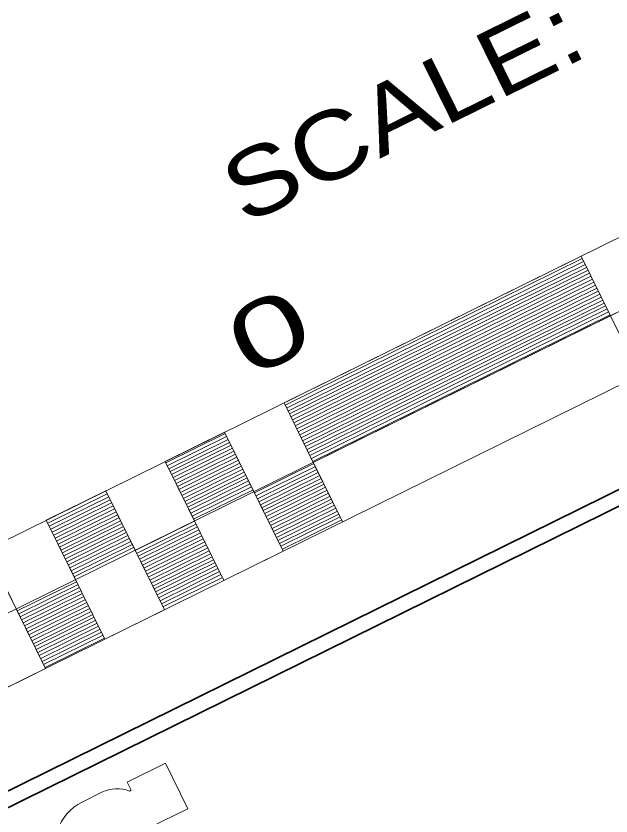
# Model space of a CAD drawing. Extents: x 2356606 to 2371222, y 6973096 to 6982644.
# Drawn here: x 2370248 to 2370337.8, y 6979398.7 to 6979519.5 of the extents above; entities that cross this region are included whole.
import ezdxf
from ezdxf.enums import TextEntityAlignment as Align

# ---------------------------------------------------------------- set-up
doc = ezdxf.new("R2010")
doc.units = 0
doc.header["$LTSCALE"] = 2
doc.layers.add('62', color=7, linetype='Continuous', lineweight=13)
doc.layers.add('63', color=7, linetype='Continuous', lineweight=13)

msp = doc.modelspace()

# ---------------------------------------------------------------- linework, layer by layer
at = {"layer": '62', "lineweight": 35}
msp.add_line((2370772.563, 6979661.979), (2370188.769, 6979373.856), dxfattribs=at)
at = {"layer": '62'}
for p, q in [((2370198.776, 6979416.806), (2370557.503, 6979593.85)), ((2370203.203, 6979407.838), (2370561.929, 6979584.882)), ((2370288.618, 6979460.743), (2370333.457, 6979482.874)), ((2370333.298, 6979483.197), (2370337.726, 6979474.228)), ((2370288.838, 6979460.296), (2370333.68, 6979482.426)), ((2370289.06, 6979459.846), (2370333.901, 6979481.977)), ((2370289.282, 6979459.399), (2370334.123, 6979481.529)), ((2370289.502, 6979458.951), (2370334.343, 6979481.08)), ((2370289.724, 6979458.501), (2370334.566, 6979480.631)), ((2370289.945, 6979458.053), (2370334.787, 6979480.184)), ((2370290.166, 6979457.606), (2370335.007, 6979479.734)), ((2370290.389, 6979457.157), (2370335.228, 6979479.286)), ((2370290.61, 6979456.708), (2370335.449, 6979478.838)), ((2370290.83, 6979456.26), (2370335.671, 6979478.389)), ((2370291.053, 6979455.812), (2370335.892, 6979477.941)), ((2370291.274, 6979455.363), (2370336.114, 6979477.492)), ((2370291.494, 6979454.914), (2370336.336, 6979477.045)), ((2370291.716, 6979454.466), (2370336.556, 6979476.596)), ((2370291.937, 6979454.018), (2370336.779, 6979476.147)), ((2370292.158, 6979453.569), (2370336.998, 6979475.7)), ((2370292.379, 6979453.121), (2370337.22, 6979475.252)), ((2370292.602, 6979452.673), (2370337.442, 6979474.803)), ((2370292.823, 6979452.225), (2370337.662, 6979474.355)), ((2370337.726, 6979474.228), (2370342.15, 6979465.261)), ((2370288.459, 6979461.067), (2370292.884, 6979452.099)), ((2370270.61, 6979452.038), (2370279.578, 6979456.465)), ((2370279.491, 6979456.641), (2370283.915, 6979447.673)), ((2370270.83, 6979451.589), (2370279.799, 6979456.015)), ((2370271.052, 6979451.139), (2370280.021, 6979455.566)), ((2370271.273, 6979450.691), (2370280.241, 6979455.118)), ((2370271.495, 6979450.243), (2370280.464, 6979454.669)), ((2370271.717, 6979449.794), (2370280.685, 6979454.221)), ((2370271.937, 6979449.346), (2370280.905, 6979453.772)), ((2370272.158, 6979448.898), (2370281.127, 6979453.324)), ((2370272.379, 6979448.45), (2370281.348, 6979452.876)), ((2370270.522, 6979452.214), (2370274.947, 6979443.246)), ((2370272.601, 6979448.002), (2370281.569, 6979452.427)), ((2370272.823, 6979447.553), (2370281.791, 6979451.979)), ((2370273.043, 6979447.105), (2370282.013, 6979451.53)), ((2370284.003, 6979447.495), (2370292.973, 6979451.922)), ((2370292.884, 6979452.1), (2370297.311, 6979443.131)), ((2370292.884, 6979452.099), (2370297.311, 6979443.132)), ((2370273.266, 6979446.656), (2370282.234, 6979451.082)), ((2370273.487, 6979446.208), (2370282.455, 6979450.633)), ((2370284.226, 6979447.047), (2370293.194, 6979451.472)), ((2370284.446, 6979446.598), (2370293.415, 6979451.026)), ((2370284.667, 6979446.15), (2370293.637, 6979450.578)), ((2370273.708, 6979445.76), (2370282.676, 6979450.185)), ((2370273.929, 6979445.311), (2370282.897, 6979449.737)), ((2370274.15, 6979444.863), (2370283.119, 6979449.288)), ((2370284.888, 6979445.702), (2370293.858, 6979450.128)), ((2370285.11, 6979445.253), (2370294.078, 6979449.681)), ((2370285.332, 6979444.805), (2370294.3, 6979449.231)), ((2370274.371, 6979444.414), (2370283.34, 6979448.84)), ((2370274.593, 6979443.966), (2370283.562, 6979448.392)), ((2370274.815, 6979443.518), (2370283.782, 6979447.943)), ((2370285.552, 6979444.356), (2370294.521, 6979448.783)), ((2370285.774, 6979443.908), (2370294.744, 6979448.335)), ((2370285.995, 6979443.459), (2370294.965, 6979447.887)), ((2370252.59, 6979443.352), (2370261.559, 6979447.779)), ((2370252.811, 6979442.903), (2370261.781, 6979447.33)), ((2370253.034, 6979442.453), (2370262.001, 6979446.88)), ((2370261.554, 6979447.789), (2370265.98, 6979438.821)), ((2370283.916, 6979447.674), (2370288.343, 6979438.706)), ((2370283.916, 6979447.673), (2370288.342, 6979438.704)), ((2370286.215, 6979443.011), (2370295.185, 6979447.439)), ((2370286.437, 6979442.563), (2370295.407, 6979446.99)), ((2370253.256, 6979442.005), (2370262.222, 6979446.433)), ((2370253.476, 6979441.557), (2370262.444, 6979445.983)), ((2370253.697, 6979441.109), (2370262.666, 6979445.535)), ((2370286.659, 6979442.115), (2370295.627, 6979446.542)), ((2370286.88, 6979441.666), (2370295.85, 6979446.094)), ((2370287.102, 6979441.217), (2370296.071, 6979445.644)), ((2370253.919, 6979440.662), (2370262.887, 6979445.087)), ((2370254.14, 6979440.212), (2370263.108, 6979444.638)), ((2370287.323, 6979440.769), (2370296.292, 6979445.196)), ((2370287.545, 6979440.322), (2370296.513, 6979444.747)), ((2370287.765, 6979439.873), (2370296.735, 6979444.298)), ((2370252.585, 6979443.362), (2370257.011, 6979434.395)), ((2370254.362, 6979439.764), (2370263.33, 6979444.19)), ((2370254.583, 6979439.316), (2370263.55, 6979443.742)), ((2370254.803, 6979438.867), (2370263.773, 6979443.294)), ((2370265.984, 6979438.81), (2370274.953, 6979443.237)), ((2370287.986, 6979439.424), (2370296.956, 6979443.851)), ((2370288.208, 6979438.975), (2370297.177, 6979443.402)), ((2370255.024, 6979438.42), (2370263.994, 6979442.844)), ((2370255.246, 6979437.97), (2370264.214, 6979442.396)), ((2370255.468, 6979437.522), (2370264.436, 6979441.948)), ((2370266.206, 6979438.363), (2370275.175, 6979442.789)), ((2370266.427, 6979437.914), (2370275.397, 6979442.341)), ((2370266.649, 6979437.466), (2370275.618, 6979441.892)), ((2370255.689, 6979437.074), (2370264.657, 6979441.5)), ((2370255.91, 6979436.625), (2370264.879, 6979441.052)), ((2370266.869, 6979437.017), (2370275.838, 6979441.444)), ((2370267.091, 6979436.569), (2370276.061, 6979440.996)), ((2370256.132, 6979436.177), (2370265.099, 6979440.603)), ((2370256.352, 6979435.729), (2370265.321, 6979440.155)), ((2370256.575, 6979435.281), (2370265.543, 6979439.707)), ((2370267.313, 6979436.121), (2370276.282, 6979440.547)), ((2370267.533, 6979435.672), (2370276.503, 6979440.099)), ((2370267.754, 6979435.223), (2370276.724, 6979439.65)), ((2370243.617, 6979438.938), (2370248.043, 6979429.968)), ((2370256.796, 6979434.832), (2370265.763, 6979439.258)), ((2370265.979, 6979438.821), (2370270.406, 6979429.852)), ((2370265.98, 6979438.822), (2370270.406, 6979429.853)), ((2370267.976, 6979434.775), (2370276.945, 6979439.202)), ((2370268.198, 6979434.327), (2370277.167, 6979438.754)), ((2370268.419, 6979433.879), (2370277.387, 6979438.305)), ((2370268.64, 6979433.43), (2370277.61, 6979437.857)), ((2370268.862, 6979432.982), (2370277.831, 6979437.409)), ((2370269.083, 6979432.533), (2370278.052, 6979436.959)), ((2370269.305, 6979432.084), (2370278.274, 6979436.511)), ((2370269.526, 6979431.637), (2370278.494, 6979436.062)), ((2370269.746, 6979431.188), (2370278.716, 6979435.614)), ((2370269.968, 6979430.74), (2370278.937, 6979435.165)), ((2370270.189, 6979430.291), (2370279.158, 6979434.717)), ((2370248.195, 6979429.662), (2370257.164, 6979434.087)), ((2370248.416, 6979429.212), (2370257.385, 6979433.639)), ((2370248.637, 6979428.765), (2370257.607, 6979433.191)), ((2370248.859, 6979428.317), (2370257.828, 6979432.742)), ((2370249.08, 6979427.867), (2370258.05, 6979432.294)), ((2370249.301, 6979427.42), (2370258.271, 6979431.844)), ((2370249.522, 6979426.97), (2370258.491, 6979431.396)), ((2370248.043, 6979429.969), (2370252.468, 6979421.001)), ((2370248.043, 6979429.968), (2370252.47, 6979421)), ((2370249.744, 6979426.522), (2370258.713, 6979430.948)), ((2370249.964, 6979426.074), (2370258.934, 6979430.5)), ((2370250.186, 6979425.625), (2370259.155, 6979430.052)), ((2370250.408, 6979425.177), (2370259.377, 6979429.602)), ((2370250.629, 6979424.728), (2370259.597, 6979429.156)), ((2370250.851, 6979424.28), (2370259.82, 6979428.708)), ((2370251.07, 6979423.831), (2370260.04, 6979428.259)), ((2370251.292, 6979423.382), (2370260.262, 6979427.81)), ((2370251.514, 6979422.934), (2370260.483, 6979427.361)), ((2370251.736, 6979422.486), (2370260.704, 6979426.913)), ((2370251.957, 6979422.037), (2370260.926, 6979426.465)), ((2370252.179, 6979421.588), (2370261.147, 6979426.016)), ((2370252.399, 6979421.141), (2370261.369, 6979425.568)), ((2370257.976, 6979400.825), (2370260.966, 6979402.3))]:
    msp.add_line(p, q, dxfattribs=at)
for points in [[(2370342.15, 6979465.261), (2370386.992, 6979487.391), (2370382.566, 6979496.36), (2370337.726, 6979474.228)], [(2370292.884, 6979452.099), (2370337.726, 6979474.228), (2370333.298, 6979483.197), (2370288.459, 6979461.067)], [(2370279.374, 6979434.278), (2370288.342, 6979438.704), (2370279.491, 6979456.641), (2370270.522, 6979452.214)], [(2370261.438, 6979425.425), (2370270.406, 6979429.852), (2370261.554, 6979447.789), (2370252.585, 6979443.362)], [(2370243.502, 6979416.574), (2370252.47, 6979421), (2370243.617, 6979438.938), (2370234.648, 6979434.51)]]:
    msp.add_lwpolyline(points, close=True, dxfattribs=at)
msp.add_lwpolyline([(2370265.161, 6979402.489), (2370265.378, 6979402.596), (2370264.774, 6979403.82), (2370270.561, 6979406.676), (2370273.942, 6979399.825), (2370268.155, 6979396.969)], dxfattribs=at)
for centre, radius, start, end in [((2370263.277, 6979397.645), 5.197, 68.74309, 116.40675), ((2370261.275, 6979394.235), 7.37, 116.59512, 205.42078)]:
    msp.add_arc(centre, radius, start, end, dxfattribs=at)
at = {"layer": '63', "lineweight": 35}
msp.add_line((2370771.897, 6979659.152), (2370188.104, 6979371.029), dxfattribs=at)
at = {"layer": '63'}
for p, q in [((2370198.776, 6979416.806), (2370557.503, 6979593.85)), ((2370203.203, 6979407.838), (2370561.929, 6979584.882)), ((2370207.628, 6979398.87), (2370566.356, 6979575.913)), ((2370288.618, 6979460.743), (2370333.457, 6979482.874)), ((2370333.298, 6979483.197), (2370337.726, 6979474.228)), ((2370288.838, 6979460.296), (2370333.68, 6979482.426)), ((2370289.06, 6979459.846), (2370333.901, 6979481.977)), ((2370289.282, 6979459.399), (2370334.123, 6979481.529)), ((2370289.502, 6979458.951), (2370334.343, 6979481.08)), ((2370289.724, 6979458.501), (2370334.566, 6979480.631)), ((2370289.945, 6979458.053), (2370334.787, 6979480.184)), ((2370290.166, 6979457.606), (2370335.007, 6979479.734)), ((2370290.389, 6979457.157), (2370335.228, 6979479.286)), ((2370290.61, 6979456.708), (2370335.449, 6979478.838)), ((2370290.83, 6979456.26), (2370335.671, 6979478.389)), ((2370291.053, 6979455.812), (2370335.892, 6979477.941)), ((2370291.274, 6979455.363), (2370336.114, 6979477.492)), ((2370291.494, 6979454.914), (2370336.336, 6979477.045)), ((2370291.716, 6979454.466), (2370336.556, 6979476.596)), ((2370291.937, 6979454.018), (2370336.779, 6979476.147)), ((2370292.158, 6979453.569), (2370336.998, 6979475.7)), ((2370292.379, 6979453.121), (2370337.22, 6979475.252)), ((2370292.602, 6979452.673), (2370337.442, 6979474.803)), ((2370292.823, 6979452.225), (2370337.662, 6979474.355)), ((2370337.726, 6979474.228), (2370342.15, 6979465.261)), ((2370288.459, 6979461.067), (2370292.884, 6979452.099)), ((2370270.61, 6979452.038), (2370279.578, 6979456.465)), ((2370279.491, 6979456.641), (2370283.915, 6979447.673)), ((2370270.83, 6979451.589), (2370279.799, 6979456.015)), ((2370271.052, 6979451.139), (2370280.021, 6979455.566)), ((2370271.273, 6979450.691), (2370280.241, 6979455.118)), ((2370271.495, 6979450.243), (2370280.464, 6979454.669)), ((2370271.717, 6979449.794), (2370280.685, 6979454.221)), ((2370271.937, 6979449.346), (2370280.905, 6979453.772)), ((2370272.158, 6979448.898), (2370281.127, 6979453.324)), ((2370272.379, 6979448.45), (2370281.348, 6979452.876)), ((2370270.522, 6979452.214), (2370274.947, 6979443.246)), ((2370272.601, 6979448.002), (2370281.569, 6979452.427)), ((2370272.823, 6979447.553), (2370281.791, 6979451.979)), ((2370273.043, 6979447.105), (2370282.013, 6979451.53)), ((2370284.003, 6979447.495), (2370292.973, 6979451.922)), ((2370292.884, 6979452.1), (2370297.311, 6979443.131)), ((2370292.884, 6979452.099), (2370297.311, 6979443.132)), ((2370273.266, 6979446.656), (2370282.234, 6979451.082)), ((2370273.487, 6979446.208), (2370282.455, 6979450.633)), ((2370284.226, 6979447.047), (2370293.194, 6979451.472)), ((2370284.446, 6979446.598), (2370293.415, 6979451.026)), ((2370284.667, 6979446.15), (2370293.637, 6979450.578)), ((2370273.708, 6979445.76), (2370282.676, 6979450.185)), ((2370273.929, 6979445.311), (2370282.897, 6979449.737)), ((2370274.15, 6979444.863), (2370283.119, 6979449.288)), ((2370284.888, 6979445.702), (2370293.858, 6979450.128)), ((2370285.11, 6979445.253), (2370294.078, 6979449.681)), ((2370285.332, 6979444.805), (2370294.3, 6979449.231)), ((2370274.371, 6979444.414), (2370283.34, 6979448.84)), ((2370274.593, 6979443.966), (2370283.562, 6979448.392)), ((2370274.815, 6979443.518), (2370283.782, 6979447.943)), ((2370285.552, 6979444.356), (2370294.521, 6979448.783)), ((2370285.774, 6979443.908), (2370294.744, 6979448.335)), ((2370285.995, 6979443.459), (2370294.965, 6979447.887)), ((2370252.59, 6979443.352), (2370261.559, 6979447.779)), ((2370252.811, 6979442.903), (2370261.781, 6979447.33)), ((2370253.034, 6979442.453), (2370262.001, 6979446.88)), ((2370261.554, 6979447.789), (2370265.98, 6979438.821)), ((2370283.916, 6979447.674), (2370288.343, 6979438.706)), ((2370283.916, 6979447.673), (2370288.342, 6979438.704)), ((2370286.215, 6979443.011), (2370295.185, 6979447.439)), ((2370286.437, 6979442.563), (2370295.407, 6979446.99)), ((2370253.256, 6979442.005), (2370262.222, 6979446.433)), ((2370253.476, 6979441.557), (2370262.444, 6979445.983)), ((2370253.697, 6979441.109), (2370262.666, 6979445.535)), ((2370286.659, 6979442.115), (2370295.627, 6979446.542)), ((2370286.88, 6979441.666), (2370295.85, 6979446.094)), ((2370287.102, 6979441.217), (2370296.071, 6979445.644)), ((2370253.919, 6979440.662), (2370262.887, 6979445.087)), ((2370254.14, 6979440.212), (2370263.108, 6979444.638)), ((2370287.323, 6979440.769), (2370296.292, 6979445.196)), ((2370287.545, 6979440.322), (2370296.513, 6979444.747)), ((2370287.765, 6979439.873), (2370296.735, 6979444.298)), ((2370252.585, 6979443.362), (2370257.011, 6979434.395)), ((2370254.362, 6979439.764), (2370263.33, 6979444.19)), ((2370254.583, 6979439.316), (2370263.55, 6979443.742)), ((2370254.803, 6979438.867), (2370263.773, 6979443.294)), ((2370265.984, 6979438.81), (2370274.953, 6979443.237)), ((2370287.986, 6979439.424), (2370296.956, 6979443.851)), ((2370288.208, 6979438.975), (2370297.177, 6979443.402)), ((2370255.024, 6979438.42), (2370263.994, 6979442.844)), ((2370255.246, 6979437.97), (2370264.214, 6979442.396)), ((2370255.468, 6979437.522), (2370264.436, 6979441.948)), ((2370266.206, 6979438.363), (2370275.175, 6979442.789)), ((2370266.427, 6979437.914), (2370275.397, 6979442.341)), ((2370266.649, 6979437.466), (2370275.618, 6979441.892)), ((2370255.689, 6979437.074), (2370264.657, 6979441.5)), ((2370255.91, 6979436.625), (2370264.879, 6979441.052)), ((2370266.869, 6979437.017), (2370275.838, 6979441.444)), ((2370267.091, 6979436.569), (2370276.061, 6979440.996)), ((2370256.132, 6979436.177), (2370265.099, 6979440.603)), ((2370256.352, 6979435.729), (2370265.321, 6979440.155)), ((2370256.575, 6979435.281), (2370265.543, 6979439.707)), ((2370267.313, 6979436.121), (2370276.282, 6979440.547)), ((2370267.533, 6979435.672), (2370276.503, 6979440.099)), ((2370267.754, 6979435.223), (2370276.724, 6979439.65)), ((2370243.617, 6979438.938), (2370248.043, 6979429.968)), ((2370256.796, 6979434.832), (2370265.763, 6979439.258)), ((2370265.979, 6979438.821), (2370270.406, 6979429.852)), ((2370265.98, 6979438.822), (2370270.406, 6979429.853)), ((2370267.976, 6979434.775), (2370276.945, 6979439.202)), ((2370268.198, 6979434.327), (2370277.167, 6979438.754)), ((2370268.419, 6979433.879), (2370277.387, 6979438.305)), ((2370268.64, 6979433.43), (2370277.61, 6979437.857)), ((2370268.862, 6979432.982), (2370277.831, 6979437.409)), ((2370269.083, 6979432.533), (2370278.052, 6979436.959)), ((2370269.305, 6979432.084), (2370278.274, 6979436.511)), ((2370269.526, 6979431.637), (2370278.494, 6979436.062)), ((2370269.746, 6979431.188), (2370278.716, 6979435.614)), ((2370269.968, 6979430.74), (2370278.937, 6979435.165)), ((2370270.189, 6979430.291), (2370279.158, 6979434.717)), ((2370248.195, 6979429.662), (2370257.164, 6979434.087)), ((2370248.416, 6979429.212), (2370257.385, 6979433.639)), ((2370248.637, 6979428.765), (2370257.607, 6979433.191)), ((2370248.859, 6979428.317), (2370257.828, 6979432.742)), ((2370249.08, 6979427.867), (2370258.05, 6979432.294)), ((2370249.301, 6979427.42), (2370258.271, 6979431.844)), ((2370249.522, 6979426.97), (2370258.491, 6979431.396)), ((2370248.043, 6979429.969), (2370252.468, 6979421.001)), ((2370248.043, 6979429.968), (2370252.47, 6979421)), ((2370249.744, 6979426.522), (2370258.713, 6979430.948)), ((2370249.964, 6979426.074), (2370258.934, 6979430.5)), ((2370250.186, 6979425.625), (2370259.155, 6979430.052)), ((2370250.408, 6979425.177), (2370259.377, 6979429.602)), ((2370250.629, 6979424.728), (2370259.597, 6979429.156)), ((2370250.851, 6979424.28), (2370259.82, 6979428.708)), ((2370251.07, 6979423.831), (2370260.04, 6979428.259)), ((2370251.292, 6979423.382), (2370260.262, 6979427.81)), ((2370251.514, 6979422.934), (2370260.483, 6979427.361)), ((2370251.736, 6979422.486), (2370260.704, 6979426.913)), ((2370251.957, 6979422.037), (2370260.926, 6979426.465)), ((2370252.179, 6979421.588), (2370261.147, 6979426.016)), ((2370252.399, 6979421.141), (2370261.369, 6979425.568))]:
    msp.add_line(p, q, dxfattribs=at)
for points in [[(2370342.15, 6979465.261), (2370386.992, 6979487.391), (2370382.566, 6979496.36), (2370337.726, 6979474.228)], [(2370292.884, 6979452.099), (2370337.726, 6979474.228), (2370333.298, 6979483.197), (2370288.459, 6979461.067)], [(2370279.374, 6979434.278), (2370288.342, 6979438.704), (2370279.491, 6979456.641), (2370270.522, 6979452.214)], [(2370261.438, 6979425.425), (2370270.406, 6979429.852), (2370261.554, 6979447.789), (2370252.585, 6979443.362)], [(2370243.502, 6979416.574), (2370252.47, 6979421), (2370243.617, 6979438.938), (2370234.648, 6979434.51)]]:
    msp.add_lwpolyline(points, close=True, dxfattribs=at)

# ---------------------------------------------------------------- texts
at = {"layer": '62'}
for s, width, p in [('SCALE:  1 INCH = 100 FT.', 1.2, (2370370.377, 6979531.207)), ('0', 1.55, (2370288.459, 6979467.239))]:
    msp.add_text(s, height=10.2, rotation=26.268, dxfattribs=dict(at, width=width)).set_placement(p, align=Align.CENTER)
at = {"layer": '62', "width": 1.25}
for s, p in [('3010 LBJ Freeway, Suite 1300', (2370234.848, 6979310.249)), ('Graystone Centre', (2370225.312, 6979329.572))]:
    msp.add_text(s, height=13.22, rotation=26.268, dxfattribs=at).set_placement(p)
at = {"layer": '63', "width": 1.55}
msp.add_text('0', height=10.2, rotation=26.268, dxfattribs=at).set_placement((2370288.459, 6979467.239), align=Align.CENTER)

doc.saveas('drawing.dxf')
